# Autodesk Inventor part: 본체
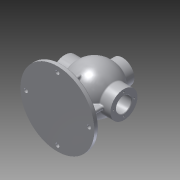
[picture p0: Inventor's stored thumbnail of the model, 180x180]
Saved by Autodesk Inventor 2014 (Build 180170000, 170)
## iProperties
Created: 2020-08
Part Number: 본체
Material: Aluminum 6061
Document SubType Name: Modeling
Designer: kh
Density: 2.71 g/cm^3
Appearance: Aluminum - Flat
Mass: 1759.18 g
Surface Area: 1342.58 cm^2
Volume: 649.145 cm^3
Author: kh
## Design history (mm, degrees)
sketch "Sketch1"
  geometry: C1 r 85 at (0, 0); 1 further point
  constraints: 1 centre point, 1 coincident
  dimensions: "d0" = 170 diameter of C1
extrude "Extrusion1" new body sketch "Sketch1" distance "d1" = 10; taper "d2" = 0 deg
sketch "Sketch2"
  geometry: L1 (-53, 85)-(53, 85); A1 r 53 centre (0, 85) between (-53, 85) and (53, 85); 3 further points
  constraints: 2 coincident, 2 end point, 2 point on circle, 1 centre point, 1 horizontal, 1 midpoint, 1 vertical alignment
  dimensions: "d4" = 85 distance of point (0, 0) point (0, 85); "d5" = 106 diameter of A1
revolve "Revolution1" sketch "Sketch2" stored, may be unused: angle "d6" = 90 deg
sketch "Sketch3"
  geometry: L1 (-68, 85)-(68, 85); L2 (-85, 0)-(85, 0) reference; L3 (-68, 85)-(-68, 116); L4 (-68, 116)-(68, 116); L5 (68, 116)-(68, 85); 3 further points
  constraints: 8 end point, 2 midpoint, 2 perpendicular, 1 horizontal, 1 parallel, 1 vertical alignment
  dimensions: "d7" = 85 distance between parallel lines of L2 L1; "d8" = 136 distance of L1.start L1.end; "d9" = 62 diameter of L4 L1
revolve "Revolution2" sketch "Sketch3" stored, may be unused: angle "d10" = 90 deg
workplane "Work Plane1"
sketch "Sketch4"
  geometry: C1 r 27 at (0, 0); 1 further point
  constraints: 1 centre point, 1 coincident
  dimensions: "d12" = 54 diameter of C1
extrude "Extrusion2" join sketch "Sketch4" stored distance "d13" = 10; taper "d14" = 0 deg
sketch "Sketch5"
  geometry: L1 (-43, 85)-(43, 85); A1 r 53 centre (0, 85) between (42.988, 116) and (42.988, 54) reference; A2 r 43 centre (0, 85) between (-43, 85) and (43, 85); 2 further points
  constraints: 2 coincident, 2 end point, 2 point on circle, 1 centre point, 1 horizontal, 1 midpoint
  dimensions: "d15" = 86 diameter of A2
revolve "Revolution3" sketch "Sketch5" stored, may be unused: angle "d16" = 90 deg
sketch "Sketch6"
  geometry: L1 (-68, 85)-(68, 85); L2 (-68, 54)-(-68, 116) reference; L3 (68, 54)-(68, 116) reference; L4 (-68, 85)-(-68, 102.5); L5 (68, 102.5)-(68, 85); L6 (-68, 102.5)-(-52, 102.5); L7 (-52, 102.5)-(-52, 103.5); L8 (-52, 103.5)-(-50.25, 103.5); L9 (-50.25, 103.5)-(-50.25, 102.5); L10 (-50.25, 102.5)-(68, 102.5); 1 further point
  constraints: 16 end point, 3 parallel, 3 perpendicular, 2 midpoint, 2 point on line, 1 collinear, 1 horizontal
  dimensions: "d17" = 85 distance from line of point (0, 0) L1; "d19" = 37 diameter of L8 L1; "d20" = 35 diameter of L10 L1; "d21" = 1.75 distance between parallel lines of L9 L7; "d22" = 16 distance from line of L6.end L2
revolve "Revolution4" sketch "Sketch6" stored, may be unused: angle "d23" = 90 deg
hole "Hole1" diameter "d26" = 26; stored, may be unused: countersink angle "d30" = 90 deg, drill point angle "d32" = 118 deg; dims "d24" = 10, "d25" = 10, "d27" = 6, "d28" = 4, "d29" = 2, "d31" = 8
chamfer "Chamfer1" distance "d33" = 1; stored, may be unused: second distance "d34" = 2, angle "d35" = 45 deg
workplane "Work Plane2"
sketch "Sketch7"
  geometry: L1 (-38.739, -5.998)-(38.739, -5.998); L2 (38.739, -5.998)-(38.739, -12.002); L3 (38.739, -12.002)-(-38.739, -12.002); L4 (-38.739, -12.002)-(-38.739, -5.998); L5 (-27, 0)-(-27, -19.393) reference; L6 (0, -12.002)-(0, -5.998); L7 (-27, 0)-(27, 0) reference; L8 (-38.739, -9)-(38.739, -9); 1 further point
  constraints: 4 end point, 4 midpoint, 2 other
  dimensions: "d37" = 9 distance between parallel lines of L7 L8; "d38" = 27 distance between parallel lines of L5 L6
emboss "Emboss1" sketch "Sketch7" dims "d39" = 0.5, "d40" = 0
sketch "Sketch8"
  geometry: L1 (52, -4)-(52, 4); L2 (-52, 4)-(-52, -4); L3 (-52, -4)-(52, 4); L4 (52, -4)-(-52, 4); L5 (-4, -43)-(4, -43); L6 (4, 43)-(-4, 43); L7 (-4, -43)-(4, 43); L8 (4, -43)-(-4, 43); L9 (-4, 4)-(-52, 4); L10 (-4, 43)-(-4, 4); L11 (52, 4)-(4, 4); L12 (-4, -4)-(-4, -43); L13 (4, -43)-(4, -4); L14 (4, 4)-(4, 43); L15 (-52, -4)-(-4, -4); L16 (4, -4)-(52, -4); 1 further point
  constraints: 32 end point, 10 parallel, 4 collinear, 4 midpoint, 4 perpendicular, 3 horizontal
  dimensions: "d41" = 104 distance of L2.start L1.end; "d42" = 86 distance between parallel lines of L5 L6; "d45" = 8 distance between parallel lines of L13 L12; "d46" = 8 distance between parallel lines of L11 L16
extrude "Extrusion3" join sketch "Sketch8" stored distance "d47" = 10; taper "d48" = 0 deg
sketch "Sketch9" dims "d49" = 48
  geometry: L1 (0, 0)-(0, 24); C1 r 31 at (0, 0) reference; 2 further points
  constraints: 2 coincident, 2 end point, 1 vertical, 1 vertical alignment, 2 other
hole "Hole2" sketch "Sketch9" at (0, 24) diameter "d50" = 3.242; stored, may be unused: countersink angle "d54" = 90 deg, drill point angle "d56" = 118 deg; dims "d51" = 12, "d52" = 4, "d53" = 2, "d55" = 15
pattern_circular "Circular Pattern1" dims angle "d58" = 360 deg
mirror "Mirror1"
sketch "Sketch10" dims "d60" = 40
  geometry: L1 (0, 0)-(0, 20); 2 further points
  constraints: 2 coincident, 2 end point, 1 vertical, 1 vertical alignment, 2 other
hole "Hole3" sketch "Sketch10" at (0, 20) diameter "d61" = 3.242; stored, may be unused: countersink angle "d65" = 90 deg, drill point angle "d67" = 118 deg; dims "d62" = 12, "d63" = 4, "d64" = 2, "d66" = 15
pattern_circular "Circular Pattern2" dims angle "d69" = 360 deg
sketch "Sketch11" dims "d71" = 145
  geometry: L1 (0, 0)-(0, 72.5); 3 further points
  constraints: 3 coincident, 2 end point, 1 vertical, 1 vertical alignment, 2 other
hole "Hole4" sketch "Sketch11" at (0, 72.5) diameter "d72" = 9; stored, may be unused: countersink angle "d76" = 90 deg, drill point angle "d78" = 118 deg; dims "d73" = 12, "d74" = 4, "d75" = 2, "d77" = 15
pattern_circular "Circular Pattern3" dims angle "d80" = 360 deg
fillet "Fillet1" dims "d82" = 3
fillet "Fillet2" dims "d83" = 3
body "Solid1"
other parameters: "d43" = 8, "d44" = 8
